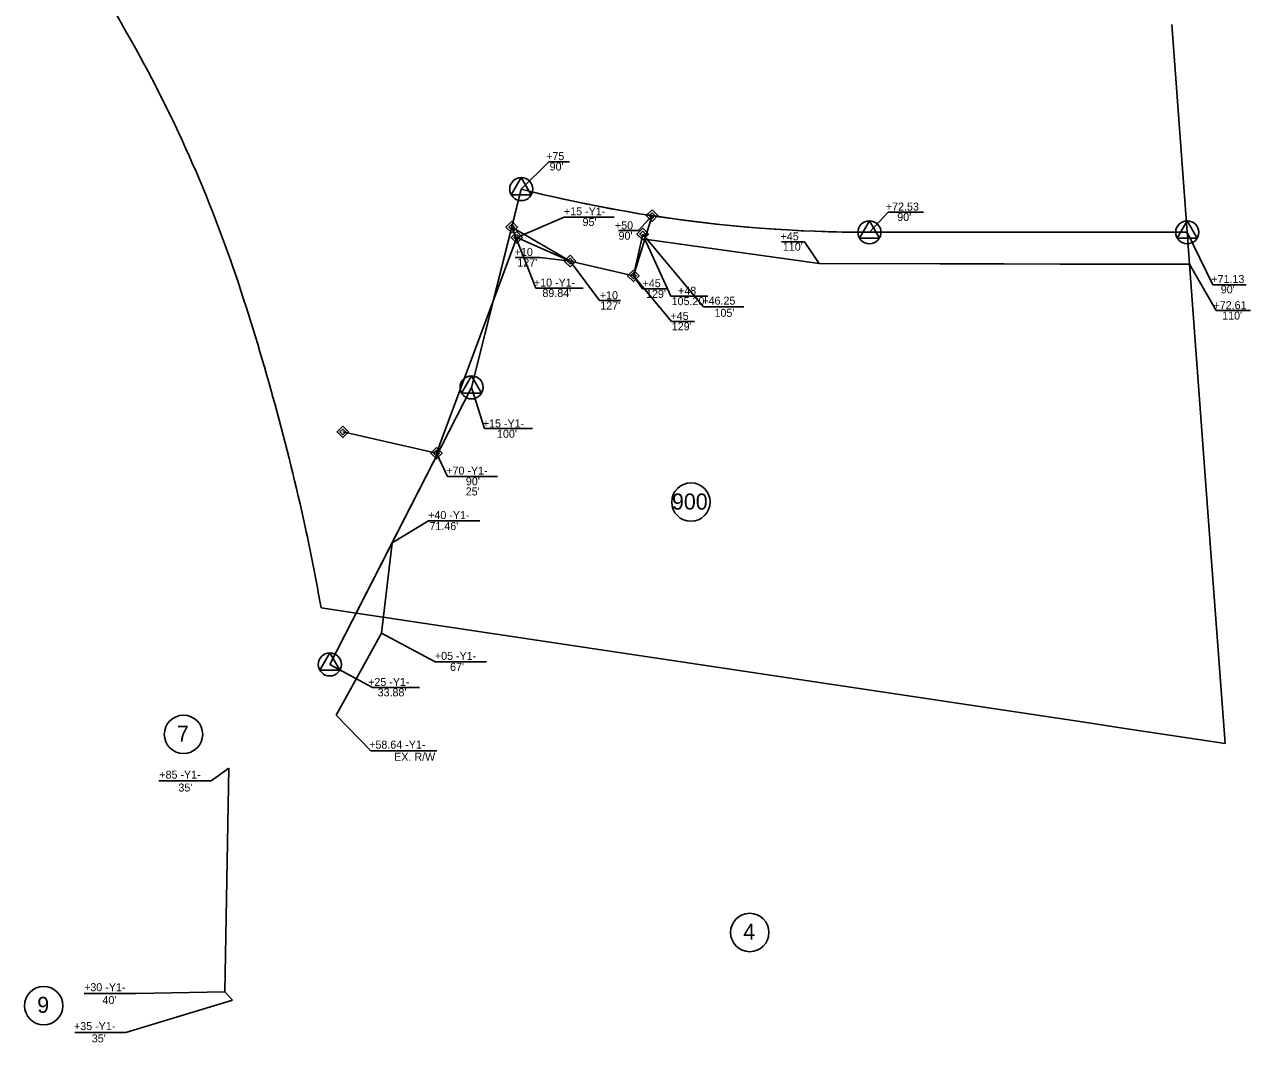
# Model space of a CAD drawing. Extents: x 1618217 to 1621927, y 897445 to 899141.
# Drawn here: x 1619272 to 1620038, y 897445 to 898081 of the extents above; entities that cross this region are included whole.
import ezdxf

# ---------------------------------------------------------------- set-up
doc = ezdxf.new("R2010")
doc.units = 0
for name, color, linetype in [('Prop Boundary Easement Permanent Drainage', 7, 'Continuous'), ('Prop Easement Construction', 7, 'Continuous'), ('Prop Easement Construction Station Offsets', 7, 'Continuous'), ('Prop Easement Permanent Drainage Station Offsets', 7, 'Continuous'), ('Prop Parcel Number CELL', 7, 'Continuous'), ('Prop ROW Marker CELL', 7, 'Continuous'), ('Prop ROW Permanent Easement CELL', 7, 'Continuous'), ('Prop ROW RW Lines', 7, 'Continuous'), ('Prop ROW Station Offsets', 7, 'Continuous'), ('Scratch_Level_0', 7, 'Continuous'), ('Scratch_Level_1', 7, 'Continuous'), ('Scratch_Level_2', 7, 'Continuous'), ('Scratch_Level_3', 7, 'Continuous'), ('Scratch_Level_4', 7, 'Continuous'), ('Scratch_Level_5', 7, 'Continuous')]:
    doc.layers.add(name, color=color, linetype=linetype)

msp = doc.modelspace()

# ---------------------------------------------------------------- linework, layer by layer
at = {"layer": 'Prop Boundary Easement Permanent Drainage'}
for p, q in [((1619652.05, 897924.02), (1619663.73, 897961.66)), ((1619576.05, 897954.54), (1619612.48, 897933.31)), ((1619612.48, 897933.31), (1619652.05, 897924.02))]:
    msp.add_line(p, q, dxfattribs=at)
at = {"layer": 'Prop Easement Construction'}
for p, q in [((1619659.18, 897946.99), (1619768.21, 897931.78)), ((1619768.21, 897931.78), (1619999.59, 897931.24))]:
    msp.add_line(p, q, dxfattribs=at)
at = {"layer": 'Prop Easement Construction Station Offsets'}
for p, q in [((1619675.35, 897911.38), (1619659.18, 897946.99)), ((1619744.61, 897945.24), (1619758.9, 897945.24)), ((1619758.9, 897945.24), (1619768.21, 897931.78)), ((1620016.09, 897902.35), (1619999.59, 897931.24)), ((1619675.35, 897911.38), (1619698.55, 897911.38)), ((1620016.09, 897902.35), (1620037.63, 897902.35))]:
    msp.add_line(p, q, dxfattribs=at)
at = {"layer": 'Prop Easement Permanent Drainage Station Offsets'}
for p, q in [((1619655.31, 897952.32), (1619663.73, 897961.66)), ((1619591.13, 897916.37), (1619576.05, 897954.54)), ((1619642.84, 897952.32), (1619655.31, 897952.32)), ((1619630.91, 897908.56), (1619612.48, 897933.31)), ((1619675.8, 897895.51), (1619652.05, 897924.02)), ((1619591.13, 897916.37), (1619620.64, 897916.37)), ((1619630.91, 897908.56), (1619643.91, 897908.56)), ((1619675.8, 897895.51), (1619690.3, 897895.51))]:
    msp.add_line(p, q, dxfattribs=at)
at = {"layer": 'Prop Parcel Number CELL'}
for p, q in [((1619688, 897782.66), (1619688, 897782.66)), ((1619724.75, 897513.68), (1619724.75, 897513.68))]:
    msp.add_line(p, q, dxfattribs=at)
for centre in [(1619688, 897782.66), (1619724.75, 897513.68)]:
    msp.add_circle(centre, 12, dxfattribs=at)
at = {"layer": 'Prop ROW Marker CELL'}
for p, q in [((1619581.99, 897978.23), (1619581.99, 897978.23)), ((1619663.73, 897961.66), (1619663.73, 897961.66)), ((1619576.05, 897954.54), (1619576.05, 897954.54)), ((1619799.51, 897951.24), (1619799.51, 897951.24)), ((1619998.11, 897951.24), (1619998.11, 897951.24)), ((1619612.48, 897933.31), (1619612.48, 897933.31)), ((1619652.05, 897924.02), (1619652.05, 897924.02)), ((1619550.92, 897854.34), (1619550.92, 897854.34)), ((1619462.37, 897681.19), (1619462.37, 897681.19))]:
    msp.add_line(p, q, dxfattribs=at)
for points in [[(1619575.74, 897974.63), (1619581.99, 897985.43), (1619588.24, 897974.63)], [(1619793.26, 897947.64), (1619799.51, 897958.44), (1619805.76, 897947.64)], [(1619991.86, 897947.64), (1619998.11, 897958.44), (1620004.36, 897947.64)], [(1619544.67, 897850.74), (1619550.92, 897861.54), (1619557.17, 897850.74)], [(1619456.12, 897677.59), (1619462.37, 897688.39), (1619468.62, 897677.59)]]:
    msp.add_lwpolyline(points, close=True, dxfattribs=at)
for centre in [(1619581.99, 897978.23), (1619799.51, 897951.24), (1619998.11, 897951.24), (1619550.92, 897854.34), (1619462.37, 897681.19)]:
    msp.add_circle(centre, 7.2, dxfattribs=at)
at = {"layer": 'Prop ROW Permanent Easement CELL'}
for points in [[(1619663.73, 897965.26), (1619667.33, 897961.66), (1619663.73, 897958.06), (1619660.13, 897961.66)], [(1619663.73, 897963.46), (1619665.53, 897961.66), (1619663.73, 897959.86), (1619661.93, 897961.66)], [(1619576.05, 897958.14), (1619579.65, 897954.54), (1619576.05, 897950.94), (1619572.45, 897954.54)], [(1619576.05, 897956.34), (1619577.85, 897954.54), (1619576.05, 897952.74), (1619574.25, 897954.54)], [(1619612.48, 897936.91), (1619616.08, 897933.31), (1619612.48, 897929.71), (1619608.88, 897933.31)], [(1619612.48, 897935.11), (1619614.28, 897933.31), (1619612.48, 897931.51), (1619610.68, 897933.31)], [(1619652.05, 897927.62), (1619655.65, 897924.02), (1619652.05, 897920.42), (1619648.45, 897924.02)], [(1619652.05, 897925.82), (1619653.85, 897924.02), (1619652.05, 897922.22), (1619650.25, 897924.02)]]:
    msp.add_lwpolyline(points, close=True, dxfattribs=at)
at = {"layer": 'Prop ROW RW Lines'}
for p, q in [((1619550.92, 897854.34), (1619581.99, 897978.23)), ((1619799.51, 897951.24), (1619998.11, 897951.24)), ((1619462.37, 897681.19), (1619550.92, 897854.34))]:
    msp.add_line(p, q, dxfattribs=at)
msp.add_arc((1619799.51, 898841.24), 890, 255.85309, 270, dxfattribs=at)
at = {"layer": 'Prop ROW Station Offsets'}
for p, q in [((1619599.12, 897995.24), (1619581.99, 897978.23)), ((1619599.12, 897995.24), (1619612.15, 897995.24)), ((1619811.18, 897963.82), (1619799.51, 897951.24)), ((1619811.18, 897963.82), (1619833.41, 897963.82)), ((1620014.04, 897918.44), (1619998.11, 897951.24)), ((1620014.04, 897918.44), (1620034.97, 897918.44)), ((1619559, 897828.57), (1619550.92, 897854.34)), ((1619559, 897828.57), (1619589.07, 897828.57)), ((1619489.01, 897666.79), (1619462.37, 897681.19)), ((1619489.01, 897666.79), (1619518.45, 897666.79))]:
    msp.add_line(p, q, dxfattribs=at)
at = {"layer": 'Scratch_Level_0'}
for p, q in [((1619608.89, 897960.75), (1619579.21, 897948.09)), ((1619608.89, 897960.75), (1619640.03, 897960.75)), ((1619529.02, 897813.24), (1619579.21, 897948.09)), ((1619579.21, 897948.09), (1619579.21, 897948.09)), ((1619652.05, 897924.02), (1619657.85, 897950.17)), ((1619695.92, 897904.58), (1619657.85, 897950.17)), ((1619657.85, 897950.17), (1619657.85, 897950.17)), ((1619578.1, 897935.4), (1619593.55, 897935.4)), ((1619593.55, 897935.4), (1619612.48, 897933.31)), ((1619612.48, 897933.31), (1619612.48, 897933.31)), ((1619657.77, 897915.82), (1619652.05, 897924.02)), ((1619652.05, 897924.02), (1619652.05, 897924.02)), ((1619657.77, 897915.82), (1619673.59, 897915.82)), ((1619695.92, 897904.58), (1619721.09, 897904.58)), ((1619470.51, 897826.52), (1619529.02, 897813.24)), ((1619470.51, 897826.52), (1619470.51, 897826.52)), ((1619535.98, 897798.73), (1619529.02, 897813.24)), ((1619529.02, 897813.24), (1619529.02, 897813.24)), ((1619535.98, 897798.73), (1619567.12, 897798.73)), ((1619370.94, 897637.51), (1619370.94, 897637.51)), ((1619388.26, 897608.39), (1619399.22, 897616.48)), ((1619396.82, 897476.53), (1619399.22, 897616.48)), ((1619355.45, 897608.39), (1619388.26, 897608.39)), ((1619308.8, 897475.56), (1619341.29, 897475.56)), ((1619334.97, 897451.23), (1619401.57, 897471.45)), ((1619341.29, 897475.56), (1619396.82, 897476.53)), ((1619401.57, 897471.45), (1619396.82, 897476.53)), ((1619283.61, 897467.96), (1619283.61, 897467.96)), ((1619303.03, 897451.23), (1619334.97, 897451.23))]:
    msp.add_line(p, q, dxfattribs=at)
for points in [[(1619657.85, 897953.77), (1619661.45, 897950.17), (1619657.85, 897946.57), (1619654.25, 897950.17)], [(1619579.21, 897951.69), (1619582.81, 897948.09), (1619579.21, 897944.49), (1619575.61, 897948.09)], [(1619579.21, 897949.89), (1619581.01, 897948.09), (1619579.21, 897946.29), (1619577.41, 897948.09)], [(1619657.85, 897951.97), (1619659.65, 897950.17), (1619657.85, 897948.37), (1619656.05, 897950.17)], [(1619612.48, 897936.91), (1619616.08, 897933.31), (1619612.48, 897929.71), (1619608.88, 897933.31)], [(1619612.48, 897935.11), (1619614.28, 897933.31), (1619612.48, 897931.51), (1619610.68, 897933.31)], [(1619652.05, 897927.62), (1619655.65, 897924.02), (1619652.05, 897920.42), (1619648.45, 897924.02)], [(1619652.05, 897925.82), (1619653.85, 897924.02), (1619652.05, 897922.22), (1619650.25, 897924.02)], [(1619470.51, 897830.12), (1619474.11, 897826.52), (1619470.51, 897822.92), (1619466.91, 897826.52)], [(1619470.51, 897828.32), (1619472.31, 897826.52), (1619470.51, 897824.72), (1619468.71, 897826.52)], [(1619529.02, 897816.84), (1619532.62, 897813.24), (1619529.02, 897809.64), (1619525.42, 897813.24)], [(1619529.02, 897815.04), (1619530.82, 897813.24), (1619529.02, 897811.44), (1619527.22, 897813.24)]]:
    msp.add_lwpolyline(points, close=True, dxfattribs=at)
msp.add_lwpolyline([(1619579.21, 897948.09), (1619612.48, 897933.31), (1619652.05, 897924.02)], dxfattribs=at)
for centre in [(1619370.94, 897637.51), (1619283.61, 897467.96)]:
    msp.add_circle(centre, 12, dxfattribs=at)
at = {"layer": 'Scratch_Level_1'}
for p, q in [((1619501.27, 897757.25), (1619524.05, 897770.86)), ((1619524.05, 897770.86), (1619556.05, 897770.86)), ((1619494.73, 897700.67), (1619501.27, 897757.25)), ((1619466.32, 897649.53), (1619494.73, 897700.67)), ((1619494.73, 897700.67), (1619528.24, 897682.87)), ((1619528.24, 897682.87), (1619560.23, 897682.87)), ((1619466.32, 897649.53), (1619487.96, 897627.15)), ((1619487.96, 897627.15), (1619529.2, 897627.15))]:
    msp.add_line(p, q, dxfattribs=at)
at = {"layer": 'Scratch_Level_2'}
for p, q in [((1619576.05, 897954.54), (1619550.92, 897854.34)), ((1619612.48, 897933.31), (1619576.05, 897954.54)), ((1619659.18, 897946.99), (1619652.05, 897924.02)), ((1619768.21, 897931.78), (1619659.18, 897946.99)), ((1619652.05, 897924.02), (1619612.48, 897933.31)), ((1619918.68, 897931.43), (1619768.21, 897931.78)), ((1619942.91, 897931.37), (1619918.68, 897931.43)), ((1619999.59, 897931.24), (1619942.91, 897931.37)), ((1620012.07, 897762.38), (1619999.59, 897931.24)), ((1619550.92, 897854.34), (1619478.81, 897713.33)), ((1620021.72, 897631.84), (1620012.07, 897762.38)), ((1619956.43, 897641.64), (1620021.72, 897631.84))]:
    msp.add_line(p, q, dxfattribs=at)
msp.add_lwpolyline([(1619478.81, 897713.33), (1619935.23, 897644.82), (1619956.43, 897641.64)], dxfattribs=at)
at = {"layer": 'Scratch_Level_3'}
for p, q in [((1619998.11, 897951.24), (1619988.51, 898081.1)), ((1619941.53, 897951.24), (1619998.11, 897951.24)), ((1619478.81, 897713.33), (1619550.92, 897854.34)), ((1619456.87, 897716.63), (1619478.81, 897713.33))]:
    msp.add_line(p, q, dxfattribs=at)
for points in [[(1619550.92, 897854.34), (1619576.05, 897954.54), (1619581.99, 897978.23)], [(1619799.51, 897951.24), (1619917.46, 897951.24), (1619941.53, 897951.24)]]:
    msp.add_lwpolyline(points, dxfattribs=at)
for centre, radius, start, end in [((1616896.2, 896683.3), 2808.85, 29.71835, 32.15687), ((1618588.73, 897649.41), 860, 18.25329, 29.71835), ((1619799.51, 898841.24), 890, 255.85309, 270), ((1617947.69, 897437.99), 1535, 12.3818, 18.25329), ((1618353.04, 897526.98), 1120, 9.74891, 12.3818)]:
    msp.add_arc(centre, radius, start, end, dxfattribs=at)
at = {"layer": 'Scratch_Level_4'}
for p, q in [((1619663.73, 897961.66), (1619659.18, 897946.99)), ((1619659.18, 897946.99), (1619768.21, 897931.78)), ((1619917.46, 897951.24), (1619799.51, 897951.24)), ((1619941.53, 897951.24), (1619917.46, 897951.24)), ((1619998.11, 897951.24), (1619941.53, 897951.24)), ((1619999.59, 897931.24), (1619998.11, 897951.24)), ((1619768.21, 897931.78), (1619918.68, 897931.43)), ((1619918.68, 897931.43), (1619942.91, 897931.37)), ((1619942.91, 897931.37), (1619999.59, 897931.24))]:
    msp.add_line(p, q, dxfattribs=at)
msp.add_arc((1619799.51, 898841.24), 890, 261.22457, 270, dxfattribs=at)
at = {"layer": 'Scratch_Level_5'}
for p, q in [((1619581.99, 897978.23), (1619576.05, 897954.54)), ((1619659.18, 897946.99), (1619663.73, 897961.66)), ((1619652.05, 897924.02), (1619659.18, 897946.99))]:
    msp.add_line(p, q, dxfattribs=at)
msp.add_lwpolyline([(1619576.05, 897954.54), (1619612.48, 897933.31), (1619652.05, 897924.02)], dxfattribs=at)
msp.add_arc((1619799.51, 898841.24), 890, 255.85309, 261.22457, dxfattribs=at)

# ---------------------------------------------------------------- texts
at = {"layer": 'Prop Easement Construction Station Offsets'}
for s, p in [('+45', (1619744.03, 897946.23)), ("110'", (1619745.44, 897939.73)), ('+48', (1619679.98, 897912.23)), ("105.20'", (1619675.94, 897905.73)), ('+72.61', (1620014.5, 897903.19)), ("110'", (1620019.95, 897896.69))]:
    msp.add_text(s, height=5, rotation=360, dxfattribs=at).set_placement(p)
at = {"layer": 'Prop Easement Permanent Drainage Station Offsets'}
for s, p in [('+50', (1619640.51, 897953.1)), ("90'", (1619642.79, 897946.6)), ('+10 -Y1-', (1619589.89, 897917.32)), ("89.84'", (1619595.2, 897910.82)), ('+10', (1619631.06, 897909.46)), ("127'", (1619631.37, 897902.96)), ('+45', (1619675.23, 897896.49)), ("129'", (1619676.04, 897889.99))]:
    msp.add_text(s, height=5, rotation=360, dxfattribs=at).set_placement(p)
at = {"layer": 'Prop Parcel Number CELL'}
for s, p in [('900', (1619676.15, 897778)), ('4', (1619720.68, 897509.21))]:
    msp.add_text(s, height=10, dxfattribs=at).set_placement(p)
at = {"layer": 'Prop ROW Station Offsets'}
for s, p in [('+75', (1619597.54, 897996.34)), ("90'", (1619599.72, 897989.84)), ('+72.53', (1619809.8, 897964.81)), ("90'", (1619816.92, 897958.31)), ('+71.13', (1620013.15, 897919.56)), ("90'", (1620019.07, 897913.06)), ('+15 -Y1-', (1619557.96, 897829.33)), ("100'", (1619566.84, 897822.83)), ('+25 -Y1-', (1619486.33, 897667.75)), ("33.88'", (1619492.24, 897661.25))]:
    msp.add_text(s, height=5, rotation=360, dxfattribs=at).set_placement(p)
at = {"layer": 'Scratch_Level_0'}
for s, p in [('+15 -Y1-', (1619608.66, 897961.85)), ("95'", (1619620.29, 897955.19)), ('+10', (1619577.86, 897936.5)), ("127'", (1619579.55, 897929.84)), ('+45', (1619657.78, 897916.93)), ("129'", (1619659.96, 897910.27)), ('+46.25', (1619695.13, 897906.04)), ("105'", (1619702.73, 897898.44)), ('+70 -Y1-', (1619535.15, 897799.84)), ("25'", (1619547.31, 897786.82)), ("90'", (1619547.38, 897793.18)), ('+85 -Y1-', (1619355.83, 897609.85)), ("35'", (1619367.76, 897601.78)), ('+30 -Y1-', (1619308.85, 897477.02)), ("40'", (1619320.3, 897468.99)), ('+35 -Y1-', (1619302.53, 897452.69)), ("35'", (1619313.65, 897445.03))]:
    msp.add_text(s, height=5, rotation=360, dxfattribs=at).set_placement(p)
for s, p in [('7', (1619366.88, 897633.04)), ('9', (1619279.55, 897463.49))]:
    msp.add_text(s, height=10, dxfattribs=at).set_placement(p)
at = {"layer": 'Scratch_Level_1'}
for s, p in [('+40 -Y1-', (1619523.83, 897772.05)), ("71.46'", (1619524.62, 897765.17)), ('+05 -Y1-', (1619528.02, 897684.07)), ("67'", (1619537.49, 897677.18)), ('+58.64 -Y1-', (1619486.98, 897628.6)), ('EX. R/W', (1619502.57, 897621.01))]:
    msp.add_text(s, height=5, rotation=360, dxfattribs=at).set_placement(p)

doc.saveas('drawing.dxf')
